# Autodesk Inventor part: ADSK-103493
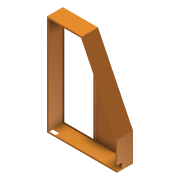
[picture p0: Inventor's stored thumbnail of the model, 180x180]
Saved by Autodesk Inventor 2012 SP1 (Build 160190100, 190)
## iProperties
Shininess: 20.0
Created: 2001-03
Part Number: ADSK-103493
Document SubType Name: Modeling
Designer: Administrator
Stock Number: ADSK-103493
Density: 1 g/cm^3
Material: Default
Density: 0.0
Volumn: 0.0
Area: 0.0
PropertySet Name: Model Information
Control State: 0
Master: False
Checked Out: False
Author: Administrator
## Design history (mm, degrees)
sketch "Sketch1"
  geometry: L1 (-174.217, -398.936)-(384.583, -398.936); L2 (943.383, -1544.646)-(943.383, -1999.136); L3 (943.383, -1999.136)-(-174.217, -1999.136); L4 (-174.217, -1999.136)-(-174.217, -398.936); L5 (384.583, -398.936)-(943.383, -1544.646)
  constraints: 10 end point, 2 parallel, 1 horizontal, 1 perpendicular
  dimensions: "d1" = 1600.2 distance of L3.end L1.start; "d85" = 1117.6 distance of L2.end L3.end; "d86" = 558.8 distance of L1.start L1.end; "d88" = 26 deg angle of L4 L5
extrude "Extrusion1" new body sketch "Sketch1" distance "d2" = 254; taper "d3" = 0 deg
shell "Shell1" dims "d4" = 3.048
sketch "Sketch2"
  geometry: L1 (384.583, -398.936)-(943.383, -1544.646) reference; L2 (-174.217, -1999.136)-(-174.217, -398.936) reference; L3 (943.383, -1999.136)-(-174.217, -1999.136) reference; L4 (943.383, -1544.646)-(943.383, -1999.136) reference; L5 (-174.217, -398.936)-(384.583, -398.936) reference; L6 (368.711, -424.336)-(917.983, -1550.51); L7 (917.983, -1550.51)-(917.983, -1973.736); L8 (917.983, -1973.736)-(-148.817, -1973.736); L9 (-148.817, -1973.736)-(-148.817, -424.336); L10 (-148.817, -424.336)-(368.711, -424.336)
  constraints: 10 end point, 4 other
  dimensions: "d90" = 25.4 distance between parallel lines of L2 L9
extrude "Extrusion2" join sketch "Sketch2" distance "d6" = 3.048; taper "d7" = 0 deg
sketch "Sketch5"
  geometry: L1 (-943.383, -1999.136)-(174.217, -1999.136) reference; L2 (174.217, -1999.136)-(174.217, -398.936) reference; L3 (-359.183, -424.336)-(148.817, -424.336); L4 (148.817, -424.336)-(148.817, -1973.736); L5 (148.817, -1973.736)-(-359.183, -1973.736); L6 (-359.183, -1973.736)-(-359.183, -424.336); L7 (-943.383, -1544.646)-(-943.383, -1999.136) reference; L8 (174.217, -398.936)-(-384.583, -398.936) reference; 1 further point
  constraints: 8 end point, 1 point on line, 1 other
  dimensions: "d91" = 25.4 distance between parallel lines of L1 L5; "d94" = 25.4 distance between parallel lines of L8 L3 (= d92); "d139" = 508 distance between parallel lines of L4 L6
extrude "Extrusion5" cut sketch "Sketch5" distance "d15" = 25.4; taper "d16" = 0 deg
sketch "Sketch6"
  geometry: L1 (530.352, -1571.752)-(22.352, -1571.752) reference; L2 (22.352, -1571.752)-(22.352, -22.352) reference; L3 (533.4, -19.304)-(19.304, -19.304); L4 (19.304, -19.304)-(19.304, -1574.8); L5 (19.304, -1574.8)-(533.4, -1574.8); L6 (0, 0)-(553.847, 0) reference; L7 (533.4, -1574.8)-(533.4, -19.304); L8 (466.725, 0)-(466.725, 30.436); L9 (22.352, -22.352)-(530.352, -22.352) reference; L10 (530.352, -22.352)-(530.352, -1571.752) reference
  constraints: 10 end point, 1 point on line, 1 other
  dimensions: "d95" = 3.048 distance between parallel lines of L2 L4; "d97" = 3.048 distance between parallel lines of L1 L5 (derived); "d140" = 3.048 distance between parallel lines of L9 L3; "d141" = 3.048 distance between parallel lines of L7 L10
extrude "Extrusion6" join sketch "Sketch6" distance "d18" = 22.352; taper "d19" = 0 deg
sketch "Sketch7"
  geometry: L1 (530.352, -1571.752)-(22.352, -1571.752) reference; L2 (22.352, -1571.752)-(22.352, -22.352) reference; L3 (533.4, -1574.8)-(19.304, -1574.8) reference; L4 (44.704, -1549.4)-(508, -1549.4); L5 (44.704, -44.704)-(44.704, -1549.4); L6 (1066.8, -1206.853)-(1066.8, -1199.9); L7 (530.352, -22.352)-(530.352, -1571.752) reference; L8 (508, -1549.4)-(508, -44.704); L9 (441.325, -22.352)-(441.325, -19.304); L10 (508, -44.704)-(44.704, -44.704); L11 (22.352, -22.352)-(530.352, -22.352) reference
  constraints: 12 end point
  dimensions: "d20" = 25.4 distance between parallel lines of L3 L4; "d105" = 22.352 distance between parallel lines of L2 L5; "d143" = 22.352 distance between parallel lines of L11 L10; "d144" = 22.352 distance between parallel lines of L7 L8
extrude "Extrusion7" join sketch "Sketch7" distance "d21" = 3.048; taper "d22" = 0 deg
sketch "Sketch8"
  geometry: L1 (-174.217, -1999.136)-(-174.217, -398.936) reference; L2 (-174.217, -398.936)-(384.583, -398.936) reference; L3 (943.383, -1544.646)-(943.383, -1999.136) reference; L4 (943.383, -1999.136)-(-174.217, -1999.136) reference; L5 (384.583, -398.936)-(943.383, -1544.646) reference; 16 further points
  dimensions: "d27" = 266.7 distance of point (-161.517, -411.636) point (105.183, -411.636); "d28" = 266.7 distance of point (105.183, -411.636) point (371.883, -411.636) (= d27); "d62" = 266.7 distance of point (371.883, -1986.436) point (638.583, -1986.436) (= d64); "d63" = 266.7 distance of point (105.183, -1986.436) point (371.883, -1986.436) (= d64); "d64" = 266.7 distance of point (-161.517, -1986.436) point (105.183, -1986.436); "d111" = 266.7 distance of point (638.583, -1986.436) point (905.283, -1986.436) (= d64); "d113" = 127 vertical distance of point (905.283, -1986.436) point (930.683, -1859.436); "d114" = 304.8 distance of point (930.683, -1859.436) point (930.683, -1554.636); "d117" = 393.7 distance of point (-161.517, -411.636) point (-161.517, -805.336); "d118" = 393.7 distance of point (-161.517, -805.336) point (-161.517, -1199.036) (= d117); "d119" = 393.7 distance of point (-161.517, -1199.036) point (-161.517, -1592.736) (= d117); "d124" = 0 horizontal distance of point (-161.517, -1199.036) point (-161.517, -1592.736); "d126" = 393.7 distance of point (-161.517, -1986.436) point (-161.517, -1592.736) (derived); "d127" = 12.7 distance from line of L1 point (-161.517, -1986.436); "d128" = 12.7 distance from line of L1 point (-161.517, -805.336); "d129" = 12.7 distance from line of L1 point (-161.517, -411.636); "d130" = 12.7 distance from line of L2 point (-161.517, -411.636); "d131" = 12.7 distance from line of L2 point (105.183, -411.636); "d132" = 12.7 distance from line of L2 point (371.883, -411.636); "d133" = 12.7 distance from line of L3 point (930.683, -1554.636); "d134" = 12.7 distance from line of L3 point (930.683, -1859.436); "d135" = 12.7 distance from line of L4 point (638.583, -1986.436); "d136" = 12.7 distance from line of L4 point (371.883, -1986.436); "d137" = 12.7 distance from line of L4 point (105.183, -1986.436); "d138" = 12.7 distance from line of L1 point (-161.517, -1199.036); "d145" = 12.7 distance from line of L5 point (514.901, -695.1); "d146" = 12.7 distance from line of L5 point (654.084, -980.467) (= d145); "d147" = 12.7 distance from line of L5 point (793.267, -1265.834) (= d145); "d148" = 317.5 distance of point (371.883, -411.636) point (514.901, -695.1); "d149" = 317.5 distance of point (514.901, -695.1) point (654.084, -980.467) (= d148); "d150" = 317.5 distance of point (654.084, -980.467) point (793.267, -1265.834) (= d148); "d151" = 12.7 distance from line of L4 point (905.283, -1986.436); "d152" = 319.82723 distance of point (930.683, -1554.636) point (793.267, -1265.834) (derived)
hole "Hole1" sketch "Sketch8" at (-161.517, -411.636), (105.183, -411.636), (371.883, -411.636), (-161.517, -805.336), (-161.517, -1199.036), (-161.517, -1592.736), (930.683, -1554.636), (930.683, -1859.436), (905.283, -1986.436), (638.583, -1986.436), (371.883, -1986.436), (105.183, -1986.436)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 diameter "d65" = 7.14375; stored, may be unused: countersink angle "d69" = 60 deg, drill point angle "d71" = 118 deg; dims "d66" = 12.7, "d67" = 9.525, "d68" = 6.35, "d70" = 6.35
sketch "Sketch9"
  geometry: L1 (917.983, -1550.51)-(917.983, -1973.736) reference; L2 (943.383, -1544.646)-(943.383, -1999.136) reference; L3 (917.983, -1973.736)-(943.383, -1973.736); L4 (917.983, -1897.536)-(943.383, -1897.536)
  constraints: 4 end point, 3 point on line, 2 perpendicular
  dimensions: "d153" = 76.2 distance between parallel lines of L4 L3
extrude "Extrusion8" cut sketch "Sketch9" distance "d154" = 76.2; taper "d155" = 0 deg
sketch "Sketch10"
  geometry: L1 (3.048, 3.048)-(3.048, 250.952) reference; L2 (3.048, 250.952)-(1114.552, 250.952) reference; L3 (9.398, 244.602)-(110.998, 244.602); L4 (110.998, 244.602)-(110.998, 168.402); L5 (110.998, 168.402)-(9.398, 168.402); L6 (9.398, 168.402)-(9.398, 244.602)
  constraints: 8 end point, 2 parallel, 1 horizontal, 1 perpendicular
  dimensions: "d156" = 6.35 distance between parallel lines of L1 L6; "d157" = 6.35 distance between parallel lines of L2 L3; "d158" = 101.6 distance of L3.start L3.end; "d159" = 76.2 distance of L3.end L4.end
extrude "Extrusion9" cut sketch "Sketch10" distance "d160" = 76.2; taper "d161" = 0 deg
body "Solid1"
other parameters: "d60" = 254, "d61" = 254, "d92" = 25.4 (= d91), "d102" = 25.4, "d104" = 25.4, "d142" = 22.352
